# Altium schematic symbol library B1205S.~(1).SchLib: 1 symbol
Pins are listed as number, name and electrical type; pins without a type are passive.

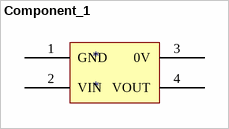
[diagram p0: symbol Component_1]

## Component_1
designator *
pins: 1 GND, 2 VIN, 3 0V, 4 VOUT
